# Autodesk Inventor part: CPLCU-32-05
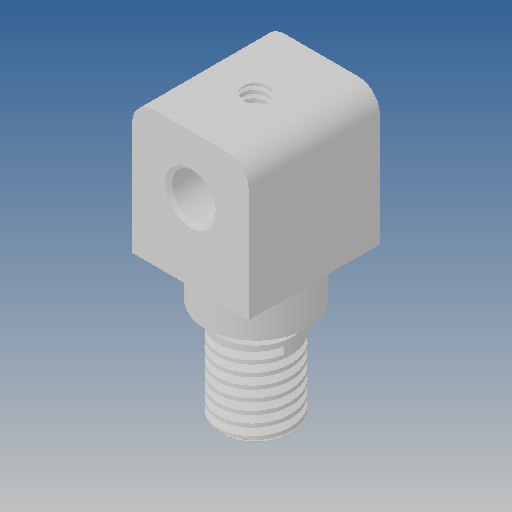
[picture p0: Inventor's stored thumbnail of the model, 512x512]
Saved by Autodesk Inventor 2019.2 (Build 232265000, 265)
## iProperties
Created: 2010-03
Part Number: CPLCU-32-05
Material: Ogólny
Document SubType Name: Modeling
Designer: CADENGINEERING4
Density: 1 g/cm^3
Appearance: Domyślna
Author: CADENGINEERING4
Revision Number: 3LAST_VERSION
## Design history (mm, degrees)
feature "Baza1"
node "Bryła1"
